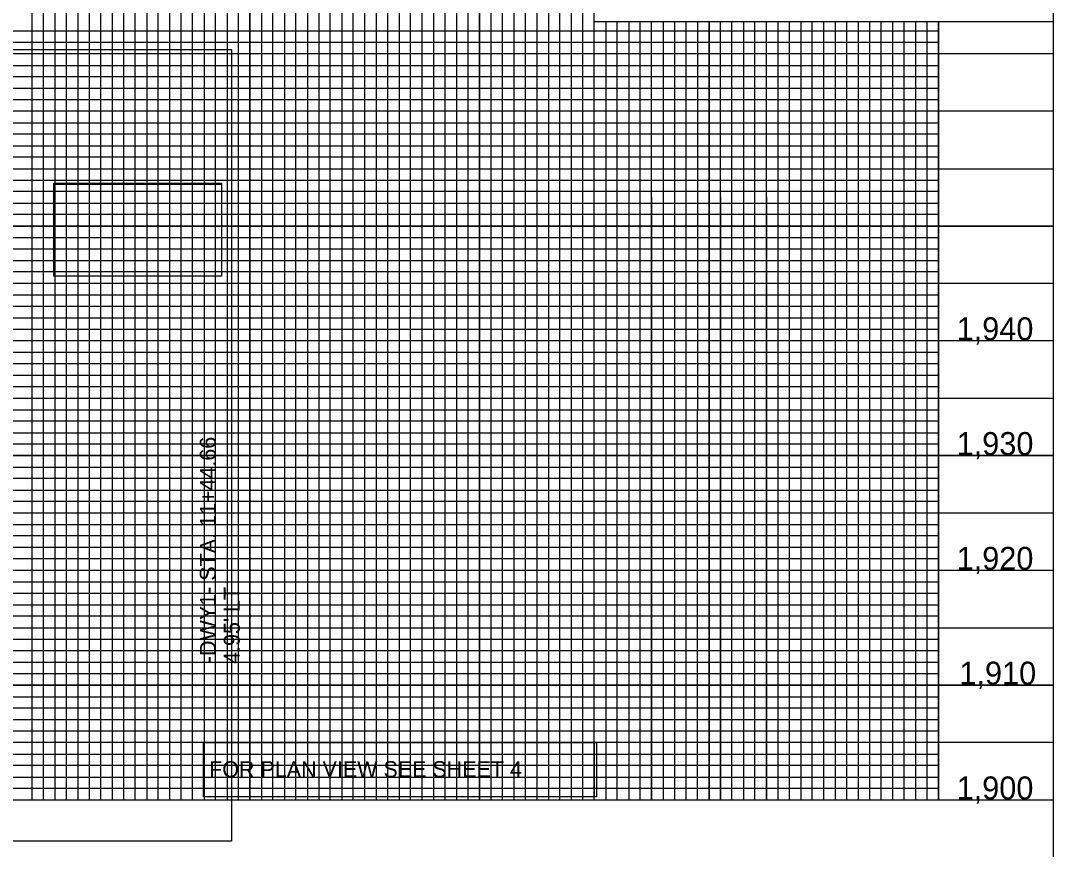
# Model space of a CAD drawing. Extents: x 557032 to 558930, y 525869 to 527437.
# Drawn here: x 558249.5 to 558699.5, y 526422.7 to 526783.7 of the extents above; entities that cross this region are included whole.
import ezdxf

# ---------------------------------------------------------------- set-up
doc = ezdxf.new("R2010")
doc.units = 0
for name, color, linetype in [('Exist Vertical Profile Vertical Axis Label', 7, 'Continuous'), ('Prop Vertical Profile Curve Label', 7, 'Continuous'), ('Prop VPI Label', 7, 'Continuous'), ('Raster_Level_4', 7, 'Continuous'), ('Sheet DOT Grid CELL', 7, 'Continuous'), ('Sheet Layout Profile Border Port 1', 7, 'Continuous'), ('Sheet Profile CELL', 7, 'Continuous'), ('Sheet Profile Grid Major CELL', 7, 'Continuous'), ('Sheet Profile Grid Middle CELL', 7, 'Continuous'), ('Sheet Profile Grid Minor CELL', 7, 'Continuous'), ('Sheet Sticker Exception Certification CELL', 7, 'Continuous')]:
    doc.layers.add(name, color=color, linetype=linetype)

msp = doc.modelspace()

# ---------------------------------------------------------------- linework, layer by layer
at = {"layer": 'Prop Vertical Profile Curve Label'}
msp.add_lwpolyline([(558264, 526712.4), (558337.06, 526712.4), (558337.06, 526672.44), (558264, 526672.44)], close=True, dxfattribs=at)
at = {"layer": 'Prop VPI Label'}
for points in [[(558264, 526712.84), (558337.06, 526712.84), (558337.06, 526672.44), (558264, 526672.44)], [(558329.22, 526469.22), (558500.36, 526469.22), (558500.36, 526445.55), (558329.22, 526445.55)], [(558329.22, 526469.22), (558499.45, 526469.22), (558499.45, 526445.55), (558329.22, 526445.55)]]:
    msp.add_lwpolyline(points, close=True, dxfattribs=at)
at = {"layer": 'Raster_Level_4'}
msp.add_lwpolyline([(557935.56, 526771.15), (558341.36, 526771.15), (558341.36, 526426.21), (557935.56, 526426.21)], close=True, dxfattribs=at)
at = {"layer": 'Sheet DOT Grid CELL'}
for p, q in [((558299.45, 526444.22), (558299.45, 526944.22)), ((558349.45, 526444.22), (558349.45, 526944.22)), ((558399.45, 526444.22), (558399.45, 526944.22)), ((558449.45, 526444.22), (558449.45, 526944.22)), ((558499.45, 526444.22), (558499.45, 526806.67)), ((558549.45, 526444.22), (558549.45, 526783.17)), ((558599.45, 526444.22), (558599.45, 526783.17)), ((558649.45, 526444.22), (558649.45, 526783.17)), ((558699.45, 526694.22), (557199.45, 526694.22)), ((558699.45, 526644.22), (557199.45, 526644.22)), ((558699.45, 526594.22), (557199.45, 526594.22)), ((558699.45, 526544.22), (557199.45, 526544.22)), ((558699.45, 526494.22), (557199.45, 526494.22))]:
    msp.add_line(p, q, dxfattribs=at)
at = {"layer": 'Sheet Layout Profile Border Port 1'}
msp.add_lwpolyline([(557249.45, 526783.17), (557249.45, 526444.22), (558649.45, 526444.22), (558649.45, 526783.17)], dxfattribs=at)
at = {"layer": 'Sheet Profile CELL'}
msp.add_line((557199.45, 526444.22), (558699.45, 526444.22), dxfattribs=at)
msp.add_lwpolyline([(558699.45, 526944.22), (557199.45, 526944.22), (557199.45, 525894.22), (558699.45, 525894.22)], close=True, dxfattribs=at)
at = {"layer": 'Sheet Profile Grid Major CELL'}
for points in [[(558249.45, 526444.22), (558299.45, 526444.22), (558299.45, 526944.22), (558349.45, 526944.22), (558349.45, 526444.22), (558399.45, 526444.22), (558399.45, 526944.22), (558449.45, 526944.22), (558449.45, 526444.22), (558499.45, 526444.22), (558499.45, 526944.22), (558525.75, 526944.22)], [(558649.45, 526783.17), (558649.45, 526444.22), (558699.45, 526444.22), (558699.45, 526794.22)], [(558549.45, 526783.17), (558549.45, 526444.22), (558599.45, 526444.22), (558599.45, 526444.22), (558599.45, 526783.17)], [(558699.45, 526744.22), (557199.45, 526744.22), (557199.45, 526694.22), (558699.45, 526694.22)], [(558699.45, 526644.22), (557199.45, 526644.22), (557199.45, 526594.22), (558699.45, 526594.22)], [(558699.45, 526544.22), (557199.45, 526544.22), (557199.45, 526544.22), (557199.45, 526494.22), (558699.45, 526494.22)]]:
    msp.add_lwpolyline(points, dxfattribs=at)
at = {"layer": 'Sheet Profile Grid Middle CELL'}
for points in [[(558224.45, 526944.22), (558274.45, 526944.22), (558274.45, 526444.22), (558324.45, 526444.22), (558324.45, 526944.22), (558374.45, 526944.22), (558374.45, 526444.22), (558424.45, 526444.22), (558424.45, 526944.22), (558474.45, 526944.22), (558474.45, 526444.22), (558524.45, 526444.22), (558524.45, 526783.17)], [(558524.45, 526707.02), (558524.45, 526444.22), (558574.45, 526444.22), (558574.45, 526783.17)], [(558574.45, 526707.02), (558574.45, 526444.22), (558624.45, 526444.22), (558624.45, 526783.17)], [(558699.45, 526769.22), (557199.45, 526769.22), (557199.45, 526719.22), (558524.45, 526719.22)], [(558524.45, 526719.22), (558699.45, 526719.22)], [(558699.45, 526669.22), (557199.45, 526669.22), (557199.45, 526619.22), (558699.45, 526619.22)], [(558699.45, 526569.22), (557199.45, 526569.22), (557199.45, 526519.22), (558699.45, 526519.22)], [(558699.45, 526469.22), (557199.45, 526469.22)]]:
    msp.add_lwpolyline(points, dxfattribs=at)
at = {"layer": 'Sheet Profile Grid Minor CELL'}
for p, q in [((557249.45, 526779.22), (558649.45, 526779.22)), ((558649.45, 526759.22), (557249.45, 526759.22)), ((557249.45, 526754.22), (558649.45, 526754.22)), ((558649.45, 526734.22), (557249.45, 526734.22)), ((557249.45, 526729.22), (558649.45, 526729.22)), ((558649.45, 526709.22), (557249.45, 526709.22)), ((557249.45, 526704.22), (558649.45, 526704.22)), ((558649.45, 526699.22), (557249.45, 526699.22)), ((557249.45, 526689.22), (558649.45, 526689.22)), ((558649.45, 526684.22), (557249.45, 526684.22)), ((557249.45, 526679.22), (558649.45, 526679.22)), ((558649.45, 526674.22), (557249.45, 526674.22)), ((557249.45, 526664.22), (558649.45, 526664.22)), ((558649.45, 526659.22), (557249.45, 526659.22)), ((557249.45, 526654.22), (558649.45, 526654.22)), ((558649.45, 526649.22), (557249.45, 526649.22)), ((557249.45, 526639.22), (558649.45, 526639.22)), ((558649.45, 526634.22), (557249.45, 526634.22)), ((557249.45, 526629.22), (558649.45, 526629.22)), ((558649.45, 526624.22), (557249.45, 526624.22)), ((557249.45, 526614.22), (558649.45, 526614.22)), ((558649.45, 526609.22), (557249.45, 526609.22)), ((557249.45, 526604.22), (558649.45, 526604.22)), ((558649.45, 526599.22), (557249.45, 526599.22)), ((557249.45, 526589.22), (558649.45, 526589.22)), ((558649.45, 526584.22), (557249.45, 526584.22)), ((557249.45, 526579.22), (558649.45, 526579.22)), ((558649.45, 526574.22), (557249.45, 526574.22)), ((557249.45, 526564.22), (558649.45, 526564.22)), ((558649.45, 526559.22), (557249.45, 526559.22)), ((558649.45, 526554.22), (557249.45, 526554.22)), ((558649.45, 526549.22), (557249.45, 526549.22)), ((557249.45, 526539.22), (558649.45, 526539.22)), ((558649.45, 526534.22), (557249.45, 526534.22)), ((557249.45, 526529.22), (558649.45, 526529.22)), ((558649.45, 526524.22), (557249.45, 526524.22)), ((557249.45, 526514.22), (558649.45, 526514.22)), ((558649.45, 526509.22), (557249.45, 526509.22)), ((557249.45, 526504.22), (558649.45, 526504.22)), ((558649.45, 526499.22), (557249.45, 526499.22)), ((557249.45, 526489.22), (558649.45, 526489.22)), ((558649.45, 526484.22), (557249.45, 526484.22)), ((557249.45, 526479.22), (558649.45, 526479.22)), ((558649.45, 526474.22), (557249.45, 526474.22)), ((557249.45, 526464.22), (558649.45, 526464.22)), ((558649.45, 526459.22), (557249.45, 526459.22)), ((557249.45, 526454.22), (558649.45, 526454.22))]:
    msp.add_line(p, q, dxfattribs=at)
for points in [[(558254.45, 526944.22), (558254.45, 526444.22), (558259.45, 526444.22), (558259.45, 526944.22)], [(558264.45, 526944.22), (558264.45, 526444.22), (558269.45, 526444.22), (558269.45, 526944.22)], [(558279.45, 526944.22), (558279.45, 526444.22), (558284.45, 526444.22), (558284.45, 526944.22)], [(558289.45, 526944.22), (558289.45, 526444.22), (558294.45, 526444.22), (558294.45, 526944.22)], [(558304.45, 526944.22), (558304.45, 526444.22), (558309.45, 526444.22), (558309.45, 526944.22)], [(558314.45, 526944.22), (558314.45, 526444.22), (558319.45, 526444.22), (558319.45, 526944.22)], [(558329.45, 526944.22), (558329.45, 526444.22), (558334.45, 526444.22), (558334.45, 526944.22)], [(558339.45, 526944.22), (558339.45, 526444.22), (558344.45, 526444.22), (558344.45, 526944.22)], [(558354.45, 526944.22), (558354.45, 526444.22), (558359.45, 526444.22), (558359.45, 526944.22)], [(558364.45, 526944.22), (558364.45, 526444.22), (558369.45, 526444.22), (558369.45, 526944.22)], [(558379.45, 526944.22), (558379.45, 526444.22), (558384.45, 526444.22), (558384.45, 526944.22)], [(558389.45, 526944.22), (558389.45, 526444.22)], [(558389.45, 526444.22), (558394.45, 526444.22), (558394.45, 526944.22)], [(558404.45, 526944.22), (558404.45, 526444.22), (558409.45, 526444.22), (558409.45, 526944.22)], [(558414.45, 526944.22), (558414.45, 526444.22), (558419.45, 526444.22), (558419.45, 526944.22)], [(558429.45, 526944.22), (558429.45, 526444.22), (558434.45, 526444.22), (558434.45, 526944.22)], [(558439.45, 526944.22), (558439.45, 526444.22), (558444.45, 526444.22), (558444.45, 526944.22)], [(558454.45, 526944.22), (558454.45, 526444.22), (558459.45, 526444.22), (558459.45, 526944.22)], [(558464.45, 526944.22), (558464.45, 526444.22), (558469.45, 526444.22), (558469.45, 526944.22)], [(558479.45, 526944.22), (558479.45, 526444.22), (558484.45, 526444.22), (558484.45, 526944.22)], [(558489.45, 526944.22), (558489.45, 526444.22), (558494.45, 526444.22), (558494.45, 526944.22)], [(558504.45, 526783.17), (558504.45, 526444.22), (558509.45, 526444.22), (558509.45, 526783.17)], [(558514.45, 526783.17), (558514.45, 526444.22), (558519.45, 526444.22), (558519.45, 526783.17)], [(558529.45, 526783.17), (558529.45, 526444.22), (558529.45, 526444.22), (558534.45, 526444.22), (558539.45, 526444.22), (558539.45, 526783.17)], [(558534.45, 526783.17), (558534.45, 526444.22)], [(558544.45, 526783.17), (558544.35, 526444.27), (558549.35, 526444.27), (558554.45, 526444.22), (558554.45, 526783.17)], [(558554.45, 526707.02), (558554.45, 526444.22), (558559.45, 526444.22), (558559.45, 526783.17)], [(558564.45, 526783.17), (558564.45, 526444.22), (558569.45, 526444.22), (558569.45, 526783.17)], [(558579.45, 526783.17), (558579.45, 526444.22), (558584.45, 526444.22), (558584.45, 526783.17)], [(558589.45, 526783.17), (558589.45, 526444.22), (558594.45, 526444.22), (558594.45, 526783.17)], [(558604.45, 526783.17), (558604.45, 526444.22), (558609.45, 526444.22), (558609.45, 526783.17)], [(558614.45, 526783.17), (558614.45, 526444.22), (558619.45, 526444.22), (558619.45, 526783.17)], [(558629.45, 526783.17), (558629.45, 526444.22), (558634.45, 526444.22), (558634.45, 526783.17)], [(558639.45, 526783.17), (558639.45, 526444.22), (558644.45, 526444.22), (558644.45, 526783.17)], [(558649.45, 526774.22), (557249.45, 526774.22), (557249.45, 526764.22), (558649.45, 526764.22)], [(558649.45, 526749.22), (557249.45, 526749.22), (557249.45, 526739.22), (558649.45, 526739.22)], [(558649.45, 526724.22), (557249.45, 526724.22), (557249.45, 526714.22), (558649.45, 526714.22)], [(558649.45, 526449.22), (557249.45, 526449.22)]]:
    msp.add_lwpolyline(points, dxfattribs=at)
at = {"layer": 'Sheet Sticker Exception Certification CELL'}
for p, q in [((558499.4, 526783.17), (558499.4, 526806.67)), ((558499.4, 526783.17), (558499.4, 526806.67)), ((558699.44, 526806.66), (558699.44, 526783.16)), ((558699.44, 526806.66), (558699.44, 526783.16)), ((558699.44, 526783.17), (558499.4, 526783.17)), ((558699.44, 526783.17), (558499.4, 526783.17))]:
    msp.add_line(p, q, dxfattribs=at)

# ---------------------------------------------------------------- texts
at = {"layer": 'Exist Vertical Profile Vertical Axis Label'}
for s, p in [('1,940', (558657.31, 526644.47)), ('1,930', (558657.31, 526594.47)), ('1,920', (558657.31, 526544.47)), ('1,910', (558658.51, 526494.47)), ('1,900', (558657.31, 526444.47))]:
    msp.add_text(s, height=10, dxfattribs=at).set_placement(p)
at = {"layer": 'Prop VPI Label'}
for s, p in [('-DWY1- STA. 11+44.66', (558334.61, 526503.84)), ("4.95' LT", (558345.03, 526503.51))]:
    msp.add_text(s, height=7, rotation=90, dxfattribs=at).set_placement(p)
msp.add_text('FOR PLAN VIEW SEE SHEET 4', height=7, dxfattribs=at).set_placement((558331.66, 526454.11))

doc.saveas('drawing.dxf')
